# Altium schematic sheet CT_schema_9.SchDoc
size 391 x 238 mm
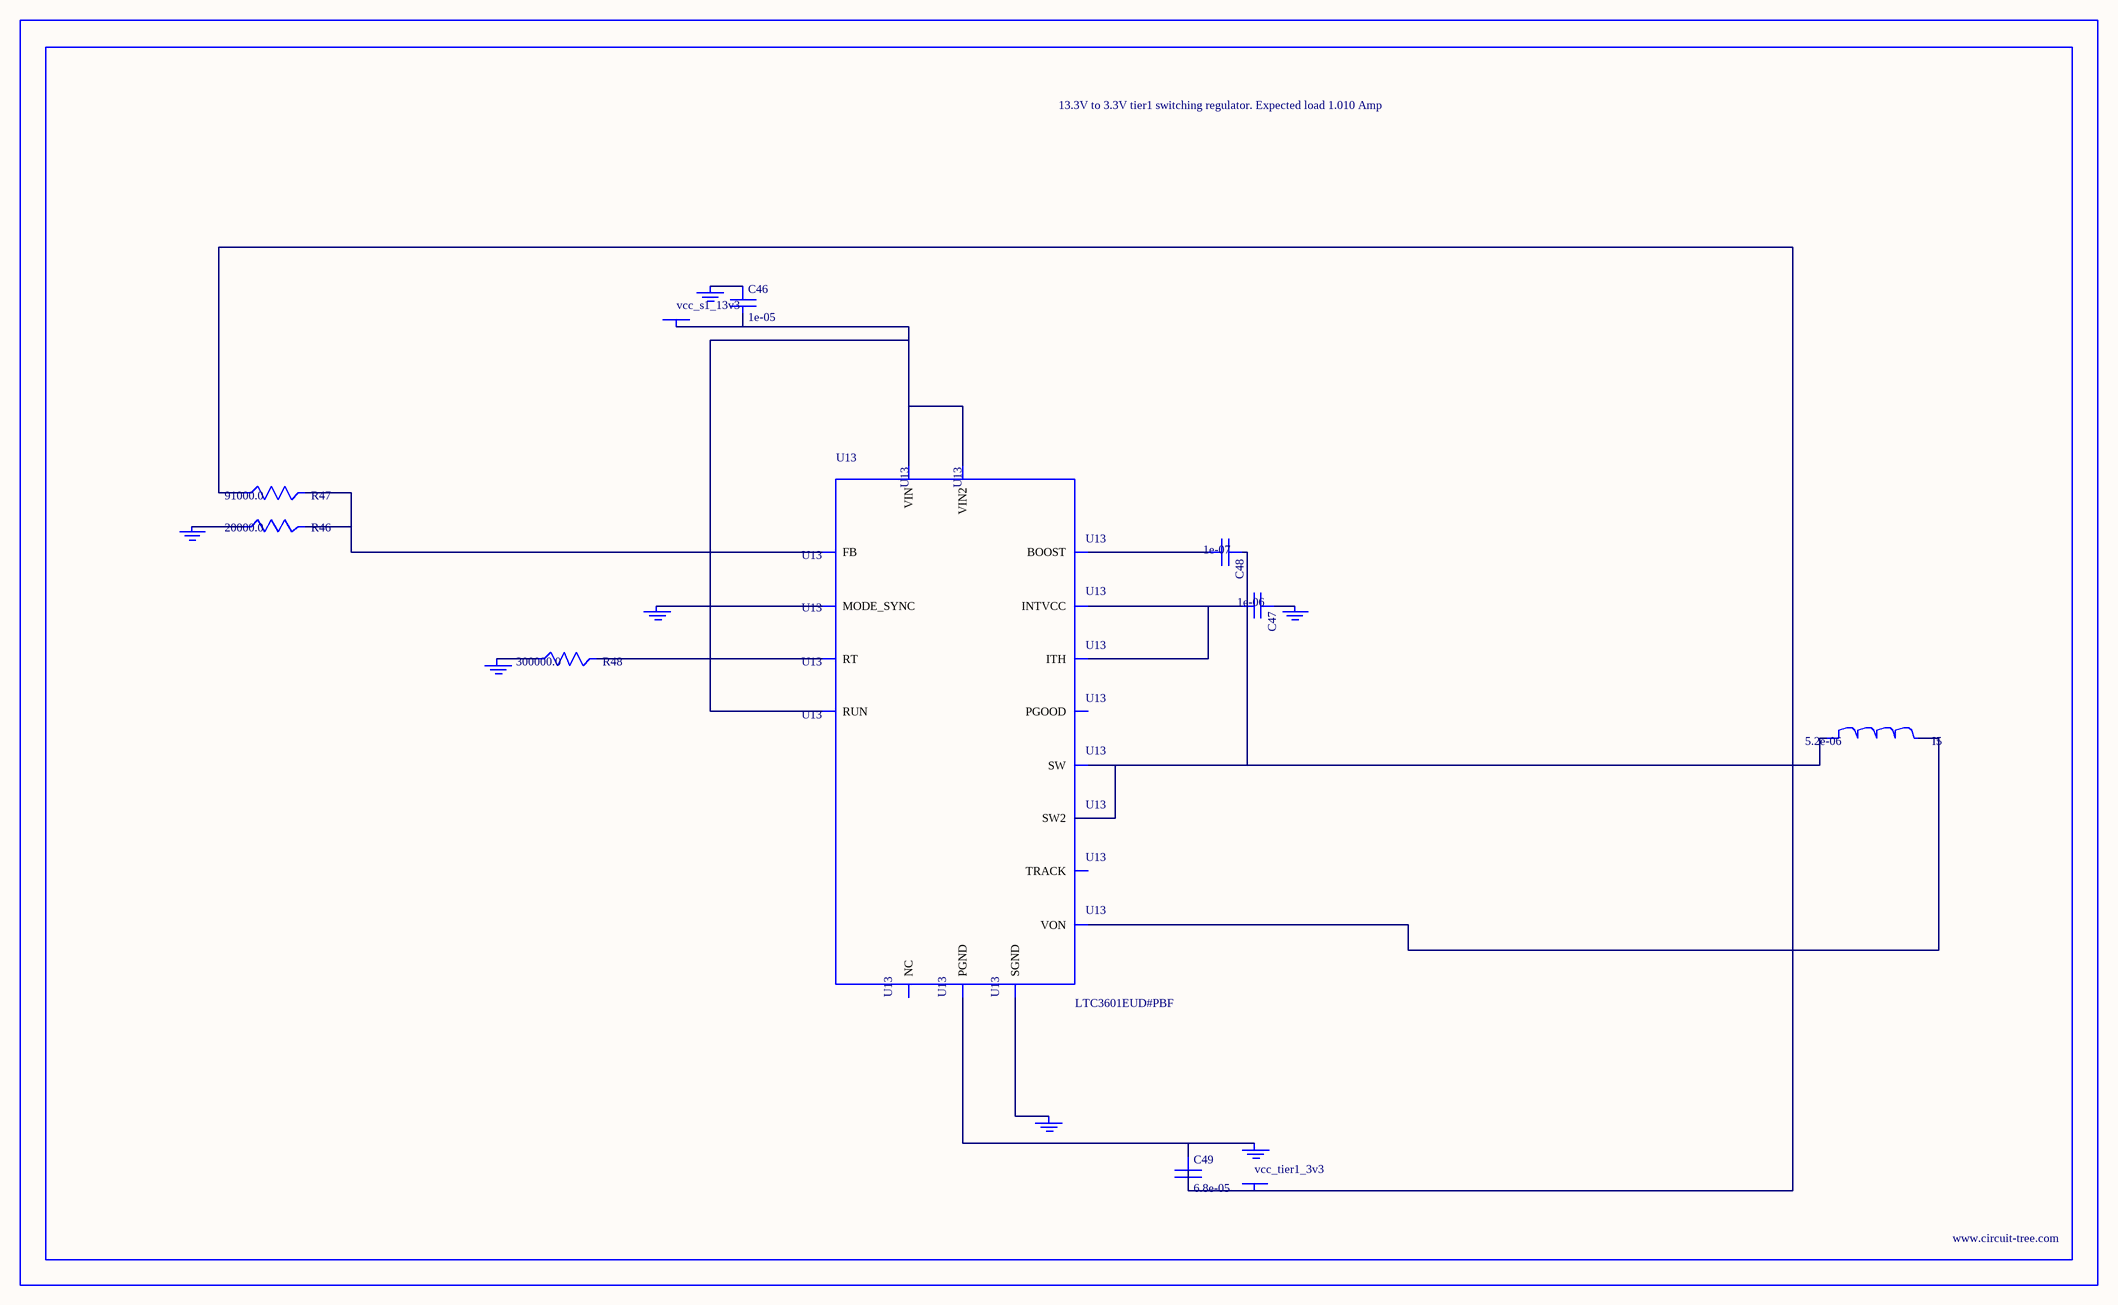
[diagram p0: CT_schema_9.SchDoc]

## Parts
BORDER8  (no value)
C46  1e-05  [C0805]
C47  1e-06  [C0603]
C48  1e-07  [C0402]
C49  6.8e-05  [2220]
GND_INSTANCE_8_0  (no value)
GND_INSTANCE_8_1  (no value)
GND_INSTANCE_8_2  (no value)
GND_INSTANCE_8_3  (no value)
GND_INSTANCE_8_4  (no value)
GND_INSTANCE_8_5  (no value)
GND_INSTANCE_8_6  (no value)
I5  5.2e-06  [DR1040]
POWER_INSTANCE_8_0  vcc_s1_13v3
POWER_INSTANCE_8_1  vcc_tier1_3v3
R46  20000.0  [R0603]
R47  91000.0  [R0603]
R48  300000.0  [R0603]
U13  LTC3601EUD#PBF  [QFN-16_EP]

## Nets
NetC46_1: C46.1 GND_INSTANCE_8_5.0(GND)
NetC46_2: C46.2 POWER_INSTANCE_8_0.0(PWR) U13.14(RUN) U13.15(VIN) U13.16(VIN2)
NetC47_1: C47.1 GND_INSTANCE_8_1.0(GND)
NetC47_2: C47.2 U13.7(INTVCC) U13.12(ITH)
NetC48_1: C48.1 I5.1 U13.3(SW) U13.4(SW2)
NetC48_2: C48.2 U13.6(BOOST)
NetC49_1: C49.1 GND_INSTANCE_8_6.0(GND) U13.17(PGND)
NetC49_2: C49.2 I5.2 POWER_INSTANCE_8_1.0(PWR) R47.1 U13.8(VON)
NetGND_INSTANCE_8_0_0: GND_INSTANCE_8_0.0(GND) U13.1(MODE_SYNC)
NetGND_INSTANCE_8_2_0: GND_INSTANCE_8_2.0(GND) U13.9(SGND)
NetGND_INSTANCE_8_3_0: GND_INSTANCE_8_3.0(GND) R48.1
NetGND_INSTANCE_8_4_0: GND_INSTANCE_8_4.0(GND) R46.1
NetR46_2: R46.2 R47.2 U13.11(FB)
NetR48_2: R48.2 U13.10(RT)

Not connected (* = marked no-connect by the designer): U13 2(PGOOD) 5(NC) 13(TRACK)

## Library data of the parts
BORDER8 = BORDER_PAGE8
C46 = C0805C106K8RACTU
C47 = C0603C105K3RACTU
C48 = C0402C104K3RACTU
C49 = C5750X5R1A686M
GND_INSTANCE_8_0-GND_INSTANCE_8_6 = GND
I5 = DR1040-5R2-R
POWER_INSTANCE_8_0 POWER_INSTANCE_8_1 = PWR
R46 = RC0603JR-0720KL
R47 = RC0603JR-0791KL
R48 = RC0603JR-07300KL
